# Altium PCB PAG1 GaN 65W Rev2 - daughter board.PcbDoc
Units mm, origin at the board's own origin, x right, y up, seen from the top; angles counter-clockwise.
Board outline 36.9 x 22.51 mm, 2 copper layers (Top Layer, Bottom Layer); 45 components, 39 nets, 158 pads, 87 vias.
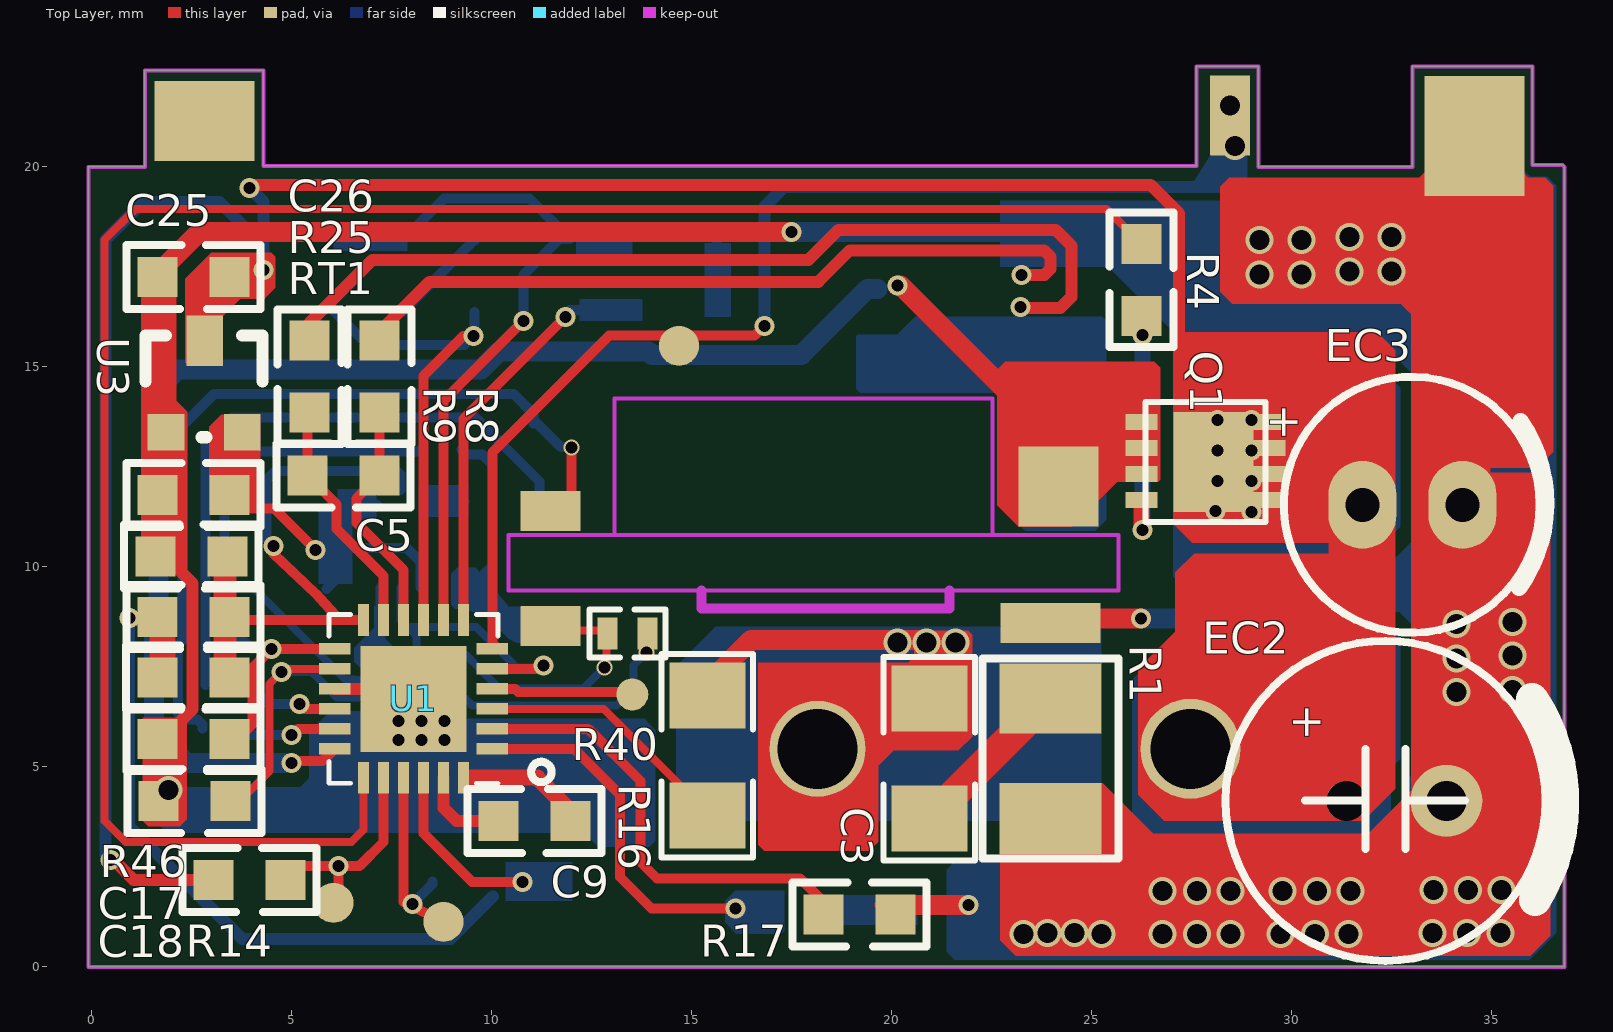
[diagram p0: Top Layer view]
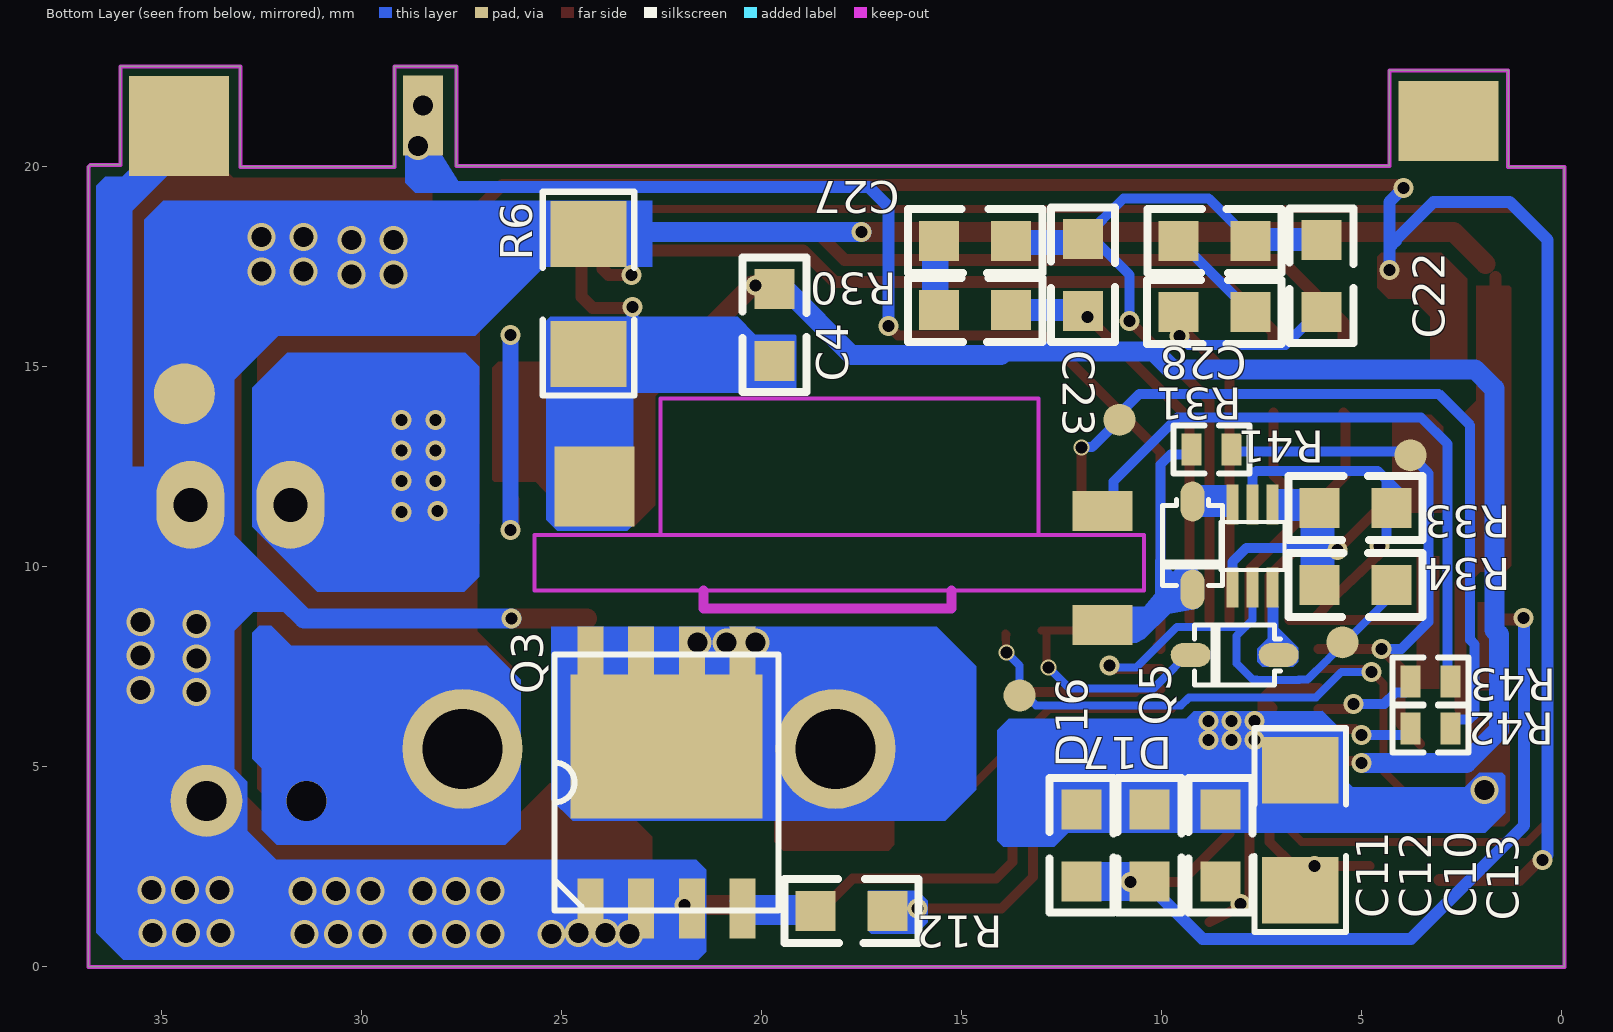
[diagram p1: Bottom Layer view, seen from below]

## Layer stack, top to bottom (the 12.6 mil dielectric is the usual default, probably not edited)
Top Solder: solder mask 0.0102, Solder Resist, Dk 3.5
Top Layer: signal copper 0.0356
Dielectric 1: dielectric 0.32, FR-4, Dk 4.8
Bottom Layer: signal copper 0.0356
Bottom Solder: solder mask 0.0102, Solder Resist, Dk 3.5

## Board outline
-0.07,0 -0.07,20 1.338,20 1.338,22.408 4.305,22.408 4.305,20.025 27.63,20.025 27.63,22.508 29.18,22.508 29.18,20 33.03,20 33.03,22.508 36.03,22.508 36.03,20.05 36.78,20.05 36.83,20 36.83,0

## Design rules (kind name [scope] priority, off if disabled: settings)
Clearance [All] p1: gap=0.254 ignorepadtopadclearanceinfootprint=FALSE except(0: Arc-Hole Track-Hole SMDPad-Hole THPad-Hole Via-Hole Fill-Hole Poly-Hole Region-Hole Text-Hole)
PolygonConnect [All] p1: connectstyle=Relief reliefconductorwidth=0.254 reliefentries=4 polygonreliefangle="90 Angle" airgapwidth=0.254
RoutingVias [All] p1: holewidth=0.711 width=1.27 viastyle="Through Hole" minholewidth=0.711 minwidth=1.27 maxholewidth=0.711 maxwidth=1.27
SolderMaskExpansion [All] p1: expansion=0.102 istentingtop=FALSE
Width [All] p1: maxlimit=0.254 minlimit=0.254 preferedwidth=0.254
30 further rules are at their usual default settings.

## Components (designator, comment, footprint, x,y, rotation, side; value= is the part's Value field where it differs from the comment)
C3 "2.2NF 200V" R1206 20.955,6.707 r270 top
C4 "2.2UF/25V" WS0603 19.68,16.05 r90 bottom
C5 "0.1UF" WS0603 6.305,12.287 r180 top
C9 "0.1UF" WS0603 11.08,3.65 r0 top
C10 "1UF" WS0603 8.53,3.038 r90 bottom
C11 "4.7UF/0805" WS0603 12.005,3.038 r90 bottom
C12 "0.1UF" WS0603 10.305,3.038 r90 bottom
C13 "10UF/1206" R1206 6.534,1.913 r90 bottom
C17 "390PF 25V" WS0603 2.555,5.7 r180 top
C18 "390PF  25V" WS0603 2.58,4.144 r180 top
C22 "10PF 25V" WS0603 6.005,17.275 r90 bottom
C23 "100PF 25V" WS0603 11.963,17.3 r90 bottom
C25 "1UF 25V" WS0603 2.555,17.25 r180 top
C26 "2.2UF 10V" WS0603 2.555,11.8 r180 top
C27 "47nF25v" WS0603 14.663,18.15 r180 bottom
C28 "1nF 25V" WS0603 8.68,18.15 r180 bottom
D16 "B0520WS  0.5A20V SOD323" SOD-323 9.229,11.627 r270 bottom
D17 "B0520WS  0.5A20V SOD323" SOD-323 7.08,7.8 r0 bottom
EC2 "680UF/25V" EC8-5 32.355,4.05 r0 top
EC3 "470UF/25V" EC6-2.5 31.78,11.55 r0 top locked
Q1 "BSZ0909LS" PPAK3*3 26.255,11.675 r0 top
Q3 "BSC0805LS" DFN5X6 22.38,4.607 r180 bottom
Q5 "MOS PNP-563" SOT-563 7.73,10.525 r180 bottom
R1 "1210 10R" R1210-t 24.055,6.792 r270 top
R4 "2.2R 0603" WS0603 26.255,17.175 r90 top
R6 "5mR   1206" R1206 24.33,15.325 r90 bottom
R8 "0R" WS0603 7.205,14.753 r90 top
R9 "0R" WS0603 5.455,14.753 r90 top
R12 "2.2R 0805" WS0603 17.755,1.4 r180 bottom
R14 "0R" WS0603 3.955,2.175 r180 top
R16 "6.98K 1206" R1206 15.405,6.782 r270 top
R17 "0R" WS0603 19.205,1.307 r180 top
R25 "100k" WS0603 2.502,10.258 r180 top
R30 "40.2K" WS0603 14.663,16.425 r180 bottom
R31 "200K" WS0603 8.683,16.375 r0 bottom
R33 "100K" WS0603 5.155,11.475 r0 bottom
R34 "100K" WS0603 5.155,9.55 r0 bottom
R40 "10R" R0402 12.902,8.333 r0 top
R41 "10R" R0402 9.252,12.933 r180 bottom
R42 "10R" R0402 2.777,5.958 r0 bottom
R43 "10R" R0402 2.777,7.133 r0 bottom
R46 "100K" WS0603 2.552,7.233 r0 top
RT1 "100K" ws0603 2.555,8.75 r180 top
U1 "CYPAS111A1 QFN24" "QFN24 cypd" 8.055,6.7 r180 top
U3 "SE8536" SOT-23 1.855,13.375 r0 top

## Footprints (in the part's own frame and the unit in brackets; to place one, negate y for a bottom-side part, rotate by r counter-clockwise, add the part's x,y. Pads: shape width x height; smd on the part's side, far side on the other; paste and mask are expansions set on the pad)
DFN5X6 [mm]
  rect 0.65x1.5 smd: 1(-1.905,-3.15) 2(-0.635,-3.15) 3(0.635,-3.15) 4(1.905,-3.15)
  rect 0.65x1.4 smd: 5(1.905,3.2) 6(0.635,3.2) 7(-0.635,3.2) 8(-1.905,3.2)
  rect 4.8x3.6 smd: 8(0,0.9)
  silkscreen extent -2.8,-3.2 2.8,3.2
EC6-2.5 [mm]
  oval 1.7x2.2 hole 0.85: 1(0,0) 2(2.5,0)
  silkscreen extent -1.96,-3.2 4.6,3.2
EC8-5 [mm]
  round 1 hole 1: 1(-0.975,0.1)
  round 1.8 hole 1: 2(1.525,0.1)
  silkscreen extent -4,-3.9 4.44,4.1
PPAK3*3 [mm]
  rect 0.8x0.4 smd: 1(0,1.95) 2(0,1.3) 3(0,0.65) 4(0,0) 5(3.2,0) 6(3.2,0.65) 7(3.2,1.3) 8(3.2,1.95)
  rect 2x2.5 smd: 8(1.8,0.95)
  round 0.3 on Top Overlay: ""(-0.454,2.539)
  silkscreen extent 0.1,-0.55 3.1,2.45
"QFN24 cypd" [mm]
  rect 0.79x0.28 smd: 1(-1.97,1.25) 2(-1.97,0.75) 3(-1.97,0.25) 4(-1.97,-0.25) 5(-1.97,-0.75) 6(-1.97,-1.25) 13(1.97,-1.25) 14(1.97,-0.75) 15(1.97,-0.25) 16(1.97,0.25) 17(1.97,0.75) 18(1.97,1.25)
  rect 0.28x0.79 smd: 7(-1.25,-1.97) 8(-0.75,-1.97) 9(-0.25,-1.97) 10(0.25,-1.97) 11(0.75,-1.97) 12(1.25,-1.97) 19(1.25,1.97) 20(0.75,1.97) 21(0.25,1.97) 22(-0.25,1.97) 23(-0.75,1.97) 24(-1.25,1.97)
  rect 2.65x2.65 smd: 25(0,0)
  oct 0.025x0.025 smd: 25(0,0)
  silkscreen extent -3.45,-2.11 2.11,2.11
R0402 [mm]
  rect 0.5x0.8 smd: 1(0,0) 2(1,0)
  silkscreen extent -0.45,-0.6 1.45,0.6
R1206 [mil]
  rect 65x75 smd: 1(0,0) 2(118.11,0)
  silkscreen extent -41,-45 159,45
R1210-t [mm]
  rect 1.78x2.54 smd: 1(3.085,-0.075)
  rect 1.75x2.54 smd: 2(0.085,-0.075)
  silkscreen extent -0.91,-1.78 4.09,1.62
SOD-323 [mm]
  oval 1x0.6 smd: A(-0.006,0.002) K(2.194,0.002)
  silkscreen extent -0.06,-0.75 2.09,0.75
SOT-23 [mil]
  rect 36x36 smd: 1(0.5,-0.39) 2(75.5,-0.39)
  rect 36x50 smd: 3(38.5,89.61)
  silkscreen extent -20,-5 96,95
SOT-563 [mm]
  rect 0.3x1 smd: 1(-0.5,-1.04) 2(0,-1.04) 3(0.5,-1.04) 4(0.5,1.03) 5(0,1.03) 6(-0.5,1.03)
  silkscreen extent -0.8,-0.6 0.8,0.6
WS0603 [mm]
  rect 1x1 smd: 1(-0.9,0) 2(0.9,0)
  silkscreen extent -1.68,-0.8 1.68,0.8, body extent -1.78,-0.9 1.78,0.9, height 1.27
ws0603 [mm]
  rect 1x1 smd: 1(-0.9,0) 2(0.9,0)
  silkscreen extent -1.68,-0.8 1.68,0.8, body extent -1.78,-0.9 1.78,0.9, height 1.27

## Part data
C3 C4 C5 C9 C10 C11 C12 C13 C17 C18 C22 C23 C25 C26 C27 C28: library part CAP1, "电容"
D16 D17: library part DIODE, "二极管"
EC2 EC3: library part CAP2, "电解电容"
Q1: library part DMTH10H010LCT_5
Q3: library part MOSFET_N
R1 R4 R6 R8 R9 R12 R14 R16 R17 R25 R30 R31 R33 R34 R40 R41 R42 R43 R46: library part RES2, "电阻"
RT1: library part "RESISTOR VAR 2_4"
U1: library part PAG1S_11
U3: library part ASO241-NO-SPST_0

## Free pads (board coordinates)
  rect 2.5x2 smd far side: 0(2.83,21.15)
  rect 2.5x2 smd: 0(2.83,21.15)
  rect 1.5x1 smd: 0(11.48,8.525) 0(11.48,11.4)
  rect 1.5x1 smd far side: 0(11.48,8.55) 0(11.48,11.4)
  round 2.4 / inner round 2.4 / far side round 3 hole 2: 0(18.155,5.45)
  rect 2.5x1 smd: 0(23.98,8.6)
  rect 2x2 smd far side: 0(24.18,12.007)
  rect 2x2 smd: 0(24.18,12.007)
  rect 1x2 smd far side: 0(28.47,21.278)
  rect 1x2 smd: 0(28.47,21.278)
  rect 2.5x2.5 smd far side: 0(34.566,21.024)
  rect 2.5x3 smd: 0(34.58,20.775)
  round 0.8 smd far side: 1(3.78,12.788) 1(5.48,8.112) 1(11.055,13.675) 1(13.552,6.783)
  round 1 smd: 1(6.055,1.599) 1(8.805,1.125) 1(14.694,15.523)
  round 0.8 smd: 1(13.527,6.808)
  round 2.5 / inner round 3 / far side round 3 hole 2: 1(27.48,5.45)
  round 1.524 smd far side: 1(34.43,14.325)

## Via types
v1: diameter 0.5, hole 0.3, Top Layer to Bottom Layer, 42 vias
v2: diameter 0.7, hole 0.5, Top Layer to Bottom Layer, 42 vias
v3: diameter 0.4, hole 0.3, Top Layer to Bottom Layer, 3 vias

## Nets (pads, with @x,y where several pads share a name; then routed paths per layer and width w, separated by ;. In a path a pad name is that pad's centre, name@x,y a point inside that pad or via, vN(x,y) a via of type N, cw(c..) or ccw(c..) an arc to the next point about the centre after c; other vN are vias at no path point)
CC1: C18.1 pad.1@13.552,6.783 R40.2 U1.14 | length 16.3
  Top Layer w0.2: C18.1@3.565,4 4.455,4.89 4.455,7.075 v1(4.755,7.375) ; v1@4.755,7.45 U1.14 ; v3(13.877,7.858) 13.889,7.87 13.889,8.296 R40.2@13.877,8.308 ; R40.2@13.902,8.183 R40.2
  Bottom Layer w0.2: v1(4.755,7.375) 5.505,7.375 6.146,6.734 9.317,6.734 9.522,6.529 13.136,6.529 13.39,6.783 13.552,6.783 13.552,7.533 v3(13.877,7.858)
CC2: C17.1 pad.1@3.78,12.788 R41.2 U1.13 | length 14.9
  Top Layer w0.25: C17.1@3.54,5.575 4.03,6.065 4.03,7.477 v1(4.503,7.95) U1.13@5.752,7.95 ; U1.13@5.752,7.95 U1.13 U1.13@5.752,7.95
  Bottom Layer w0.25: pad.1@3.78,12.788 3.33,12.338 3.33,8.625 4.005,7.95 v1(4.503,7.95) ; pad.1@3.877,12.908 3.906,12.879 8.198,12.879 R41.2
DM_GPIO4: R43.2 U1.16 | length 2.7
  Top Layer w0.25: v1(5.205,6.575) 5.33,6.45 U1.16
  Bottom Layer w0.25: R43.2@3.802,7.133 3.802,6.958 3.902,6.858 4.152,6.858 4.435,6.575 v1(5.205,6.575)
DP_GPIO5: R42.2 U1.17 | length 2.5
  Top Layer w0.25: v1@5.03,5.8 5.005,5.825 5.03,5.85 5.068,5.85 5.168,5.95 U1.17@6.085,5.95
  Bottom Layer w0.25: R42.2@3.727,5.933 3.86,5.8 v1(5.005,5.8)
GPIO0: pad.1@5.48,8.112 Q5.2 R34.1 U1.5 | length 12.5
  Top Layer w0.25: U1.5 11.148,7.45 11.234,7.537 v1(11.302,7.537)
  Bottom Layer w0.2: R34.1@3.98,9.55 5.449,8.081 5.855,7.675 ; 5.88,7.65 6.351,7.179 6.562,7.179 6.571,7.169 7.614,7.169 7.623,7.179 7.721,7.179 8.13,7.587 8.13,8.275 7.905,8.5 ; Q5.2 7.73,8.675 7.905,8.5 ; v1(11.302,7.537) 11.248,7.483 10.637,7.483 9.62,8.5 7.905,8.5
GPIO3: Q5.5 R25.1 R33.1 R46.2 RT1.1 U1.12 | length 13.6
  Top Layer w0.25: R25.1@3.315,10.275 3.315,8.75 3.395,8.67 6.21,8.67 ; v1(4.555,10.525) 4.555,10.325 5.607,9.331 6.21,8.67 ; U1.12 6.21,8.67
  Bottom Layer w0.25: R33.1@4.08,11.875 4.38,12.175 ; v1(4.555,10.525) 4.38,10.7 4.38,11.475 4.38,12.175 ; Q5.5@7.73,11.925 7.73,12.303 7.633,12.4 4.605,12.4 4.38,12.175
NetC3_1: C3.1 pad.0@18.155,5.45 Q3.5 Q3.6 Q3.7 Q3.8 R16.1 | length 7.9
  Top Layer w0.5: R16.1 15.405,7.082 16.498,8.175 20.155,8.175 20.93,8.175 20.88,8.125 v2(20.88,8.107)
  Bottom Layer w0.5: Q3.8@22.655,5.7 Q3.8@24.155,5.7
  other v2: 20.155,8.107 21.605,8.107
NetC3_2: C3.2 R1.2 | length 4.3
  Top Layer w0.25: C3.2@20.945,3.975 21.27,3.975 R1.2@24.08,6.785
NetC5_1: C5.1 R8.1 U1.10 | length 5.9
  Top Layer w0.25: R8.1 C5.1 6.63,11.712 6.63,11.1 7.805,9.925 U1.10
NetC5_2: C5.2 R9.1 U1.11 | length 6
  Top Layer w0.25: R9.1 5.405,13.803 C5.2 6.13,11.563 6.13,10.95 7.305,9.775 U1.11
NetC9_1: C9.1 U1.23 | length 2.3
  Top Layer w0.3: U1.23 8.805,3.975 9.13,3.65 C9.1
NetC9_2: C9.2 U1.24 | length 3.2
  Top Layer w0.4: U1.24@9.395,4.73 11.15,4.73 C9.2@11.98,3.9
  Top Layer w0.5: C9.2 C9.2@11.98,3.9
NetC13_1: C13.1 pad.1@6.055,1.599 R14.1 U1.20 | length 5.3
  Top Layer w0.25: R14.1@4.805,2.525 v1(6.18,2.525) ; pad.1@6.055,1.599 6.18,1.724 v1(6.18,2.525) ; U1.20 7.305,3.118 6.712,2.525 v1(6.18,2.525)
NetC22_1: C22.1 R31.2 U1.9 | length 12.3
  Top Layer w0.25: U1.9 8.305,14.775 9.305,15.775 v1(9.555,15.775)
  Bottom Layer w0.25: C22.1@6.105,16.35 6.905,15.55 9.33,15.55 v1(9.555,15.775) 9.583,15.803 R31.2
NetC22_2: C22.2 C23.2 C27.2 C28.2 U1.8 | length 17.7
  Top Layer w0.25: U1.8 8.805,14.15 v1(10.805,16.15)
  Bottom Layer w0.25: C22.2@6.105,18.15 7.768,18.15 8.825,19.207 10.956,19.207 C23.2 11.705,18.2 10.805,17.3 v1(10.805,16.15)
NetC23_1: C23.1 R30.2 U1.7 | length 9.9
  Top Layer w0.25: U1.7 9.305,13.7 v1(11.855,16.25)
  Bottom Layer w0.25: C23.1@11.963,16.425 13.238,16.425
NetC26_1: C26.1 Q5.1 Q5.4 R33.2 R34.2 U3.2 | length 10.6
  Top Layer w0.25: U3.2@3.773,13.04 3.773,11.7 4.015,11.458 4.572,11.458 v1(5.605,10.425)
  Bottom Layer w0.25: v1(5.605,10.425) 6.03,10.425 6.08,10.475 ; R34.2@5.88,9.45 6.08,9.65 6.08,10.475 ; Q5.4@7.13,11.555 6.01,11.555 5.905,11.45 5.905,10.65 6.08,10.475 ; Q5.1 8.23,10.125 7.88,10.475 6.08,10.475
NetC27_1: C27.1 R30.1 | length 1.1
  Bottom Layer w0.25: 15.63,17.017 C27.1@15.63,18.15
NetC28_1: C28.1 R31.1 | length 2.6
  Bottom Layer w0.25: R31.1 9.583,18.175 C28.1@9.593,18.175
NetD16_A: D16.A Q5.6 | length 0.1
  Bottom Layer w0.25: D16.A@9.251,11.555 D16.A@9.328,11.631
NetD16_K: D16.K pad.0@11.48,8.55 R41.1 | length 3.6
  Bottom Layer w0.254: R41.1 9.252,12.931 9.375,12.808 9.777,12.808 10.027,12.558 10.027,10.008 9.927,9.908
NetD17_A: D17.A Q5.3 | length 1.8
  Bottom Layer w0.25: D17.A 7.13,7.854 7.13,8.112 7.23,8.212 Q5.3
NetD17_K: D17.K pad.0@11.48,8.525 R40.1 | length 6.6
  Top Layer w0.2: pad.0@11.48,8.525 11.597,8.408 R40.1@13.002,8.408 ; v3(12.827,7.483) 12.827,7.51 12.877,7.56 R40.1@12.877,8.333
  Bottom Layer w0.2: D17.K 9.366,7.798 9.677,7.486 9.677,7.483 10.202,6.958 12.302,6.958 v3(12.827,7.483)
NetDM_1: pad.0@11.48,11.4 R43.1 | length 16.2
  Bottom Layer w0.25: R43.1@2.855,7.05 2.855,13.075 3.513,13.733 9.602,13.733 9.648,13.687 9.856,13.479 11.206,12.129 11.206,11.674 pad.0@11.48,11.4
NetDP_1: pad.0@11.48,11.4 pad.1@11.055,13.675 R42.1 | length 20.2
  Top Layer w0.25: v3(12.002,12.983) 12.002,11.658 pad.0@12.027,11.633
  Bottom Layer w0.25: R42.1 2.777,6.056 2.652,6.181 2.32,6.181 2.173,6.328 2.173,8.059 2.287,8.173 2.287,13.538 3.075,14.326 10.553,14.326 11.052,13.827 pad.1@11.052,13.583 ; pad.1@11.055,13.675 11.737,12.993 11.992,12.993 v3(12.002,12.983)
NetGPIO1_1: U1.6 | length 29.2
  Top Layer w0.25: U1.6@10.1,8.025 U1.6 10.025,12.858 12.949,15.782 16.587,15.782 v1(16.83,16.025)
  Bottom Layer w0.3: v1(16.83,16.025) 16.83,19 17.33,19.5 23.002,19.5 ; 23.003,19.5 23.232,19.5 ; 23.233,19.5 25.427,19.5 ; 25.428,19.5 27.671,19.5 28.405,20.234 v2@28.405,20.575
  Bottom Layer w0.4: v2@28.405,20.575 v2@28.47,21.278
  other v2: 28.597,20.516 28.47,21.532
NetQ1_4: Q1.4 R4.1 | length 5.6
  Top Layer w0.4: Q1.4 26.255,10.95 v1(26.28,10.925)
  Bottom Layer w0.4: v1(26.28,10.925) v1(26.28,15.8)
NetQ3_4: Q3.4 R12.1 | length 2.2
  Bottom Layer w0.3: R12.1@18.455,1.65 20.475,1.65 Q3.4@20.65,1.65
NetR4_2: R4.2 U1.19 | length 49.3
  Top Layer w0.2: U1.19 6.805,3.425 6.505,3.125 0.855,3.125 0.33,3.65 0.33,18.175 1.102,18.947 25.383,18.947 R4.2
NetR17_2: R17.2 U1.2 | length 11.3
  Top Layer w0.25: U1.2 12.423,5.95 13.73,4.643 13.73,2.618 14.141,2.207 17.723,2.207 R17.2@18.305,1.625
NetU1_4: pad.1@13.527,6.808 U1.4 | length 3.5
  Top Layer w0.25: U1.4 10.592,6.95 10.667,6.875 pad.1@13.527,6.875
PGND: C4.1 pad.0@24.18,12.007 R6.1 R9.2 | length 29.9
  Top Layer w0.3: R9.2 5.455,16.1 7.03,17.675 17.93,17.675 18.68,18.425 24.105,18.425 24.505,18.025 24.505,16.75 24.23,16.475 23.255,16.475 v1(23.23,16.5)
  Bottom Layer w0.3: 21.009,15.15 23.03,15.15 23.68,14.5 23.68,11.775 pad.0@23.805,11.65 ; v1(23.23,16.5) 23.23,15.925 23.33,15.825
SR_GDRV: R12.2 U1.1 | length 9
  Top Layer w0.25: U1.1 12.065,5.45 13.216,4.299 13.216,2.246 14.005,1.457 v1(16.105,1.457)
  Bottom Layer w0.25: v1(16.105,1.457) v1@16.201,1.457 ; R12.2@16.844,1.411 R12.2
SR_SENSE: R16.2 U1.3 | length 6.3
  Top Layer w0.2: U1.3@9.74,6.45 U1.3 12.806,6.45 ; 12.806,6.45 14.767,4.489 R16.2@15.191,4.489
SR_VSS: C10.2 C11.2 C12.2 C13.2 C17.2 C18.2 C25.2 C26.2 EC2.2 EC3.2 pad.0@23.98,8.6 pad.0@34.58,20.775 pad.0@34.566,21.024 pad.1@34.43,14.325 Q3.1 Q3.2 Q3.3 R1.1 R6.2 R8.2 R17.1 R25.2 U1.15 U1.25 U3.1 | length 127.5
  Top Layer w0.25: U1.25@7.23,6.95 U1.25@7.48,6.7 ; 23.845,1.55 24.08,1.785 ; 24.305,1.785 v2@29.78,1.785 ; v2@26.78,1.785 v2@29.78,1.785 ; v2@27.642,1.785 v2@29.78,1.785 ; v2@28.48,1.785 v2@29.78,1.785 ; 33.805,5.95 33.805,4.15 33.805,2.675 32.915,1.785 31.48,1.785 30.642,1.785 v2@29.78,1.785 ; U1.25@7.48,6.7 7.48,6.225 7.23,6.475 U1.25@7.48,6.7
  Top Layer w0.3: 1.655,10.875 C25.2 ; C17.2@1.795,5.7 2.53,6.435 2.53,9.587 1.785,10.331 R25.2@1.905,10.331 ; C18.2@1.905,4.45 v2(1.93,4.425) ; U1.15 U1.25@7.23,6.95 ; R8.2 7.205,15.875 8.455,17.125 18.178,17.125 18.966,17.913 23.817,17.913 23.98,17.75 23.98,17.45 23.83,17.3 v1(23.255,17.3)
  Top Layer w0.5: C25.2@1.905,17.575 2.705,18.375 v1(17.505,18.375) ; R17.1@19.829,1.55 v1(21.93,1.55) ; pad.0@24.372,8.707 v1(26.248,8.707) ; EC3.2 EC3.2@34.28,12.3
  Bottom Layer w0.25: 6.18,4.025 6.205,4.05 7.955,4.05 7.98,4.075 7.98,4.45 ; v1@7.68,5.775 7.98,5.775 ; 7.905,4.45 7.98,4.45 ; 7.98,5.8 7.98,5.775 ; 9.33,5.7 8.905,5.7 8.83,5.775 7.98,5.775 ; 13.205,4.125 13.33,4 13.33,3.55 ; 13.555,3.925 13.33,3.55 ; 13.755,3.125 13.33,3.55 ; 22.282,1.9 24.772,1.9 ; EC2.2 34.28,4.55 EC3.2 ; EC3.2@33.955,11.875 EC3.2 ; 35.23,12.5 EC3.2 ; 7.98,4.45 11.53,4.45 12.493,5.413 13.395,5.413 13.395,3.615 13.33,3.55 ; 7.98,4.45 7.98,5.775
  Bottom Layer w0.3: v2(1.93,4.425) 2.053,4.302 2.262,4.302 2.306,4.258 5.697,4.258 6.18,3.775 ; 23.18,18.05 23.255,17.975 v1(23.255,17.3)
  Bottom Layer w0.5: v1(17.505,18.375) 23.58,18.375 R6.2@23.605,18.35 ; v1(26.248,8.707) 31.437,8.707 EC3.2 ; 33.13,18.375 34.63,16.875 34.63,12.925 34.83,12.725
  other v1: 7.68,5.675 8.255,5.675 8.83,5.675 7.68,6.15 8.255,6.15 8.83,6.15
  other v2: 23.305,0.825 25.255,0.825 26.78,0.825 27.642,0.825 28.48,0.825 29.73,0.825 30.592,0.825 31.43,0.825 23.905,0.85 24.58,0.85 33.53,0.85 34.392,0.85 35.23,0.85 26.78,1.9 27.642,1.9 28.48,1.9 29.78,1.9 30.642,1.9 31.48,1.9 33.555,1.925 34.417,1.925 35.255,1.925 34.13,6.875 35.53,6.925 34.13,7.713 35.53,7.787 34.13,8.575 35.53,8.625 29.205,17.313 30.255,17.313 31.455,17.388 32.505,17.388 29.205,18.175 30.255,18.175 31.455,18.25 32.505,18.25
VBUS-IN: C25.1 EC2.1 EC3.1 pad.1@27.48,5.45 Q1.5 Q1.6 Q1.7 Q1.8 R14.2 U3.3 | length 65.2
  Top Layer w0.3: v1(0.48,2.675) 0.555,2.675 1.055,2.175 R14.2 ; U3.3@2.858,15.976 2.858,16.653 C25.1 3.63,17.425 v1(4.305,17.425) ; v1@3.955,19.55 26.48,19.55 27.193,18.837 27.193,14.587 Q1.8@28.08,13.7
  Bottom Layer w0.3: v1(0.48,2.675) 0.355,2.8 0.355,18.175 1.305,19.125 3.202,19.125 4.147,18.18 4.147,18.15 4.305,17.992 ; v1(3.955,19.475) 4.305,19.125 4.305,17.992 ; v1(4.305,17.425) 4.305,17.992 ; 27.63,3.8 28.07,3.976 28.505,4.15 EC2.1 31.78,4.55 ; v1@28.33,12.925 30.405,12.925 EC3.1
  other v1: 29.005,11.375 28.105,11.4 28.155,12.142 29.005,12.142 28.155,12.908 29.005,12.908 28.155,13.675 29.005,13.675
VBUS_C: C4.2 pad.0@24.18,12.007 Q1.1 Q1.2 Q1.3 U1.18 | length 43.7
  Top Layer w0.25: v1@4.93,5.15 5.785,5.15 U1.18
  Top Layer w0.5: v1(20.155,17.032) 20.236,17.032 23.805,13.462 pad.0@23.805,12.45 ; pad.0@23.805,11.65 pad.0@23.805,12.45 ; 26.28,14.7 26.28,13.4 26.255,13.4 24.755,13.4 pad.0@23.805,12.45
  Bottom Layer w0.5: v1@4.88,5.1 2.38,5.1 1.57,5.91 1.57,8.309 1.684,8.423 1.684,14.454 2.167,14.937 9.747,14.937 10.196,15.386 13.929,15.386 14.018,15.296 17.751,15.296 19.405,16.95 C4.2@19.655,16.95
  other v1: 5.005,5.1
VCCD: C10.1 pad.1@8.805,1.125 U1.21 | length 5
  Top Layer w0.25: U1.21 7.805,1.625 8.005,1.525 pad.1@8.805,1.125
  Bottom Layer w0.25: v1(8.03,1.575) 8.53,2.075 C10.1
VDDD: C11.1 C12.1 R46.1 RT1.2 U1.22 | length 22.7
  Top Layer w0.25: U1.22 8.305,3.337 9.517,2.125 v1(10.78,2.125)
  Top Layer w0.3: v1(0.955,8.725) 0.992,8.687 RT1.2@1.905,8.687
  Bottom Layer w0.25: C12.1@10.08,2.125 C11.1@11.555,2.125
  Bottom Layer w0.3: v1(0.955,8.725) 0.941,8.711 0.941,3.526 3.767,0.7 8.98,0.7 C12.1@10.042,1.762
pads on no net: Q1.

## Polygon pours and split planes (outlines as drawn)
SR_VSS on Bottom Solder "Bottom Solder-No Net" (hatched 90Degree grid 0.5 track 0.3): 25.905,2.475 32.13,2.475 33.455,3.8 33.455,12.95 33.355,13.05 33.355,16.825 33.755,17.225 36.105,17.225 36.455,16.875 36.455,0.85 35.805,0.2 25.855,0.2 25.655,0.4 25.655,2.225
VBUS-IN on Bottom Solder "Bottom Layer-No Net 2" (hatched 90Degree grid 0.5 track 0.3): 29.98,6.55 29.605,6.175 26.53,6.175 26.055,5.7 26.055,3.475 26.355,3.175 32.005,3.175 32.33,3.5 32.33,4.942 32.755,5.367 32.755,13.642 32.155,14.242 30.48,14.242 29.98,13.742
SR_VSS on Top Solder "Bottom Layer-No Net 2" (hatched 90Degree grid 0.508 track 0.3): 36.555,19.525 36.555,0.85 35.98,0.275 23.305,0.275 22.755,0.825 22.755,4.382 22.923,4.55 25.005,4.55 26.43,3.125 32.105,3.125 32.18,3.2 33.18,4.2 33.18,4.225 33.18,19.375 33.33,19.525

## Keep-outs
Keep-Out Layer:
  lines w0.1: 13.08,10.807 13.08,14.207 22.53,14.207 22.53,10.8 ; -0.07,0 -0.07,20 1.338,20 1.338,22.408 4.305,22.408 4.305,20.025 27.63,20.025 27.63,22.508 29.18,22.508 29.18,20 33.03,20 33.03,22.508 36.03,22.508 36.03,20.05 36.78,20.05 36.83,20 36.83,0 -0.07,0 ; 10.436,9.408 10.436,10.8 25.676,10.8 25.676,9.408 10.436,9.408
  lines w0.254: 15.252,9.408 15.252,8.958 21.452,8.958 21.452,9.408

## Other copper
Top Layer:
  region net GPIO3: 3.055,10.275 3.055,6.95 3.63,6.95 3.63,10.275
  region net VDDD: 1.462,9.122 1.462,6.907 2.105,6.907 2.105,9.122
  region net NetC26_1: 4.23,13.775 4.23,11.458 4.122,11.35 3.005,11.35 2.955,11.4 2.955,13.503 3.255,13.803 4.177,13.803 4.205,13.775
  region net SR_VSS: 26.555,3.325 25.292,4.587 24.067,4.587 22.73,3.25 22.73,0.661 23.116,0.275 24.08,1.239 24.08,1.785
  region net NetC3_2: 21.18,4.45 22.78,6.05 23.68,6.05 23.68,5.9 21.74,3.96
  region net VBUS-IN: 29.055,10.331 27.574,10.331 27.105,9.862 27.105,8.381 26.299,7.575 28.155,7.575 28.155,7.725 29.205,8.775
  region net VBUS-IN: 27.366,15.862 32.152,15.862 32.605,15.41 32.605,4.45 31.805,3.65 26.827,3.65 26.174,4.303 26.174,7.45 29.055,10.331 30.938,10.331 30.938,10.6 27.53,10.6 27.055,11.075 27.055,15.551
  region net VBUS_C: 26.73,14.254 26.73,12.175 26.68,12.125 25.649,12.125 25.424,11.9 24.158,11.9
  region net VBUS_C: 26.73,13.25 26.655,13.175 25.78,13.175 25.555,12.95 25.555,12.031 24.531,11.007 23.192,11.007 22.655,11.544 22.655,14.932 22.848,15.125 26.58,15.125 26.73,14.975
  region net SR_VSS: 34.98,12.475 36.155,12.475 36.555,12.875 36.555,19.525 36.355,19.725 33.005,19.725 33.005,10.85 33.794,10.85 34.98,12.036
  region net SR_VSS: 31.93,3.325 33.005,4.4 33.005,11.55 33.805,12.35 36.155,12.35 36.48,12.025 36.48,0.775 35.98,0.275 23.116,0.275 22.755,0.636 22.755,2.562 23.518,3.325
  region net SR_VSS: 33.455,19.725 28.455,19.725 28.23,19.5 28.23,16.875 28.53,16.575 32.742,16.575 33.455,15.862 34.355,16.763 34.355,16.8
  region net SR_VSS: 2.217,3.514 2.392,3.689 2.392,6.225 1.292,6.225 1.292,3.649 1.431,3.511 1.492,3.511
  region net SR_VSS: 2.405,9.95 2.405,13.875 2.13,14.15 2.13,17.032 1.312,17.032 1.255,16.975 1.255,10.025 1.455,9.825 1.505,9.875 2.242,9.875
  region net VBUS-IN: 3.28,16.25 3.73,16.7 4.33,16.7 4.605,16.975 4.605,17.75 4.505,17.85 3.005,17.85 2.355,17.2 2.355,15.1 2.43,15.025 3.205,15.025 3.28,15.1
  region net SR_VSS: 35.83,19.825 35.83,19.4 35.78,19.35 35.655,19.475 32.955,19.475 33.48,20
  region net SR_VSS: 35.83,19.825 36.105,19.55 35.705,19.55
  region net NetC3_1: 22.03,8.307 22.03,5.757 21.68,5.407 20.061,5.407 19.68,5.026 19.68,3.132 19.455,2.907 16.826,2.907 16.68,3.053 16.68,7.607 20.43,7.607 20.58,7.757 20.58,8.157 20.83,8.407 21.93,8.407
Bottom Layer:
  region net VDDD: 10.355,2.625 10.355,1.65 12.03,1.65 12.03,2.625
  region net NetQ3_4: 18.68,1.65 18.68,1.05 20.65,1.05 20.65,1.65
  region net NetC22_2: 6.055,18.475 6.055,17.9 7.905,17.9 7.905,18.475
  region net NetD16_A: 8.18,12.05 8.18,11.25 9.43,11.25 9.43,12.05
  region net NetC26_1: 6.155,11.95 6.155,11.15 7.13,11.15 7.13,11.95
  region net NetC26_1: 5.68,11.425 5.68,9.575 6.53,9.575 6.53,11.425
  region net PGND: 23.273,14.907 23.273,11.207 25.073,11.207 25.073,14.907
  region net NetC27_1: 15.33,18.1 15.33,16.25 15.996,16.25 15.996,18.1
  region net NetC23_1: 12.205,16.7 12.205,16.15 13.781,16.15 13.781,16.7
  region net NetC22_2: 12.118,18.425 12.118,17.8 13.53,17.8 13.53,18.425
  region net VBUS-IN: 32.73,8.35 32.73,5.2 32.493,4.963 32.493,3.425 32.118,3.05 26.405,3.05 26.02,3.435 26.02,7.172 26.873,8.025 31.755,8.025 32.255,8.525 32.555,8.525
  region net SR_GDRV: 17.33,1.9 17.33,0.9 17.255,0.825 16.13,0.825 15.845,1.11 15.845,1.65 16.095,1.9
  region net NetGPIO1_1: 28.905,20.475 28.905,19.6 28.655,19.35 27.58,19.35 27.58,19.633 28.105,20.475
  region net PGND: 25.38,16.15 25.28,16.25 20.602,16.25 20.155,15.803 19.158,15.803 19.13,15.775 19.13,14.45 19.23,14.35 25.23,14.35 25.38,14.5
  region net SR_VSS: 32.705,8.875 33.18,8.4 33.43,8.4 33.43,9.225 33.38,9.275
  region net SR_VSS: 31.83,8.75 31.955,8.875 33.455,8.875 33.455,10.075 33.23,10.3 32.205,9.275 32.08,9.275
  region net VBUS-IN: 32.73,14.475 32.73,11 31.105,9.375 27.43,9.375 27.055,9.75 27.055,15 27.405,15.35 31.855,15.35
  region net NetD17_A: 7.605,7.95 7.28,8.275 7.28,9.013 7.08,9.013 7.08,8.475 6.58,7.975 6.58,7.625 6.705,7.5 7.48,7.5 7.605,7.625
  region net NetD16_K: 10.155,10.175 10.155,9.25 10.105,9.2 9.718,9.587 9.43,9.587 10.03,10.187
  region net NetD16_K: 11.2,8.107 10.623,8.107 10.436,8.197 9.801,8.832 9.105,8.95 9.005,9.05 9.005,9.825 9.155,9.975 9.618,9.975 10.436,9 11.471,9.013
  region net PGND: 25.105,15.475 25.38,15.2 25.38,11.175 25.105,10.9 23.355,10.9 23.205,11.05 23.205,15.132 23.548,15.475
  region net SR_VSS: 35.43,11.1 35.43,18.675 34.955,19.15 22.73,19.15 22.73,17.5 25.43,17.5 27.155,15.775 32.08,15.775 33.18,14.675 33.18,12.4 34.13,12.4
  region net SR_VSS: 36.63,19.178 36.63,12.5 35.73,12.5 35.73,19.168
  region net SR_VSS: 13.824,6.198 14.105,5.916 14.105,3.15 13.955,3 12.68,3 12.33,3.35 5.78,3.35 5.455,3.675 5.455,5.875 5.986,6.406 9.199,6.387 9.384,6.201
  region net SR_VSS: 32.13,2.675 32.855,3.4 32.855,4.625 33.18,4.95 33.18,12.4 33.28,12.5 36.63,12.5 36.63,0.85 35.955,0.175 21.584,0.175 21.384,0.375 21.384,2.429 21.63,2.675
  region net SR_VSS: 1.905,3.35 5.78,3.35 5.78,4.675 5.68,4.775 5.388,4.483 2.422,4.483 2.055,4.85 1.48,4.85 1.405,4.775 1.405,3.85
  region net SR_VSS: 5.235,4.505 5.805,5.075 5.805,4.7 5.53,4.425
  region net SR_VSS: 35.83,19.9 35.98,19.75 36.405,19.75 36.63,19.525 36.63,18.825 35.805,18.825 34.555,20.075 34.555,20.087
  region net NetC3_1: 25.255,4.176 24.729,3.65 15.405,3.65 14.63,4.425 14.63,7.512 15.618,8.5 25.255,8.5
